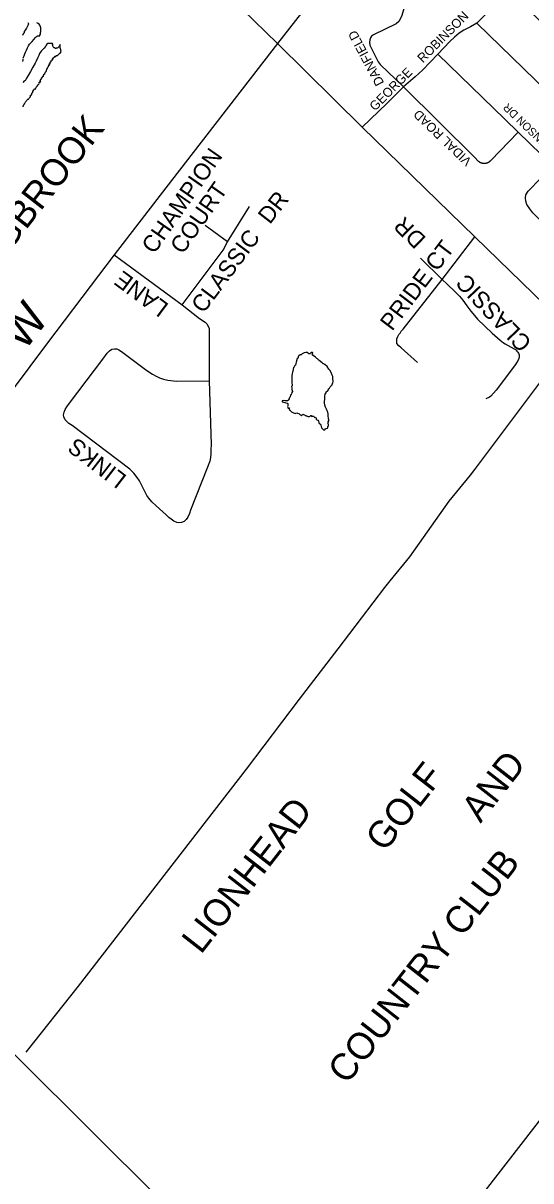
# Model space of a CAD drawing. Extents: x 586326 to 623965, y 4819854 to 4857850.
# Drawn here: x 597005 to 597763, y 4832762 to 4834491 of the extents above; entities that cross this region are included whole.
import ezdxf

# ---------------------------------------------------------------- set-up
doc = ezdxf.new("R2010")
doc.units = 0
for name, color, linetype in [('Lots_Concessions', 7, 'Continuous'), ('Major Rds and Hwys', 7, 'Continuous'), ('Major Rds Lbls', 7, 'Continuous'), ('Minor Rd Lbls', 7, 'Continuous'), ('Minor Rds', 7, 'Continuous'), ('Proposed Secondary Rds', 7, 'Continuous'), ('Pts of Interest', 7, 'Continuous'), ('SWM Ponds', 7, 'Continuous')]:
    doc.layers.add(name, color=color, linetype=linetype)

msp = doc.modelspace()

# ---------------------------------------------------------------- linework, layer by layer
at = {"layer": 'Lots_Concessions'}
for p, q in [((597679.2, 4833824.5), (597830.4, 4834026.5)), ((597673, 4833816.2), (597679.2, 4833824.5)), ((597640.9, 4833777.4), (597673, 4833816.2)), ((597582.2, 4833694.3), (597640.9, 4833777.4)), ((597553.1, 4833658.3), (597582.2, 4833694.3)), ((597475.4, 4833556.9), (597545.2, 4833648.5)), ((597545.2, 4833648.5), (597553.1, 4833658.3)), ((597417.8, 4833481.5), (597475.4, 4833556.9)), ((597338.7, 4833376.9), (597417.8, 4833481.5)), ((597088.1, 4833053.3), (597338.7, 4833376.9)), ((597010.2, 4832954.5), (597088.1, 4833053.3)), ((597478.9, 4832469.2), (597897.6, 4833009.7))]:
    msp.add_line(p, q, dxfattribs=at)
at = {"layer": 'Major Rds and Hwys'}
for points in [[(597524.5, 4834639.5), (597384.7, 4834460.6)], [(597384.7, 4834460.6), (597218.3, 4834245), (597141.1, 4834145)], [(597141.1, 4834145), (597117.7, 4834114), (597041.9, 4834013.5), (596963.5, 4833909.6)], [(597416.6, 4832528.7), (597001.7, 4832942.3), (596973.6, 4832970), (596862.2, 4833079.8)]]:
    msp.add_lwpolyline(points, dxfattribs=at)
at = {"layer": 'Minor Rds'}
for points in [[(597843.1, 4834430.7), (597738.2, 4834531.5), (597733.6, 4834533.8), (597729.6, 4834534), (597725.4, 4834532.4), (597720.6, 4834529.4), (597682.4, 4834490.7)], [(597573.4, 4834512.1), (597570.1, 4834500.9), (597565.8, 4834493.3), (597561.9, 4834489.8), (597528.3, 4834473.5), (597525.2, 4834471.3), (597523.8, 4834468.8), (597522.5, 4834466.2), (597522.1, 4834462.4), (597522.9, 4834458), (597534.9, 4834433.3), (597538.3, 4834428.9), (597572.9, 4834395.6)], [(597682.4, 4834490.7), (597672.6, 4834485.4), (597663.1, 4834480.5), (597656.1, 4834476), (597648.8, 4834470.1), (597641.9, 4834463.6), (597624.3, 4834444.5)], [(597682.4, 4834490.7), (597874.5, 4834303.9)], [(597624.3, 4834444.5), (597601, 4834420.8), (597590.1, 4834410.5), (597572.9, 4834395.6)], [(597624.3, 4834444.5), (597724.3, 4834347.4), (597744.2, 4834328.2)], [(597572.9, 4834395.6), (597548.2, 4834371.1), (597511.2, 4834335.5)], [(597572.9, 4834395.6), (597679.6, 4834289.7), (597683.9, 4834285.5), (597684, 4834285.4), (597684.1, 4834285.4), (597684.2, 4834285.3), (597684.2, 4834285.2), (597684.3, 4834285.1), (597684.4, 4834285.1), (597684.5, 4834285), (597684.5, 4834284.9), (597684.6, 4834284.9), (597684.7, 4834284.8), (597684.8, 4834284.8), (597684.8, 4834284.7), (597684.9, 4834284.6), (597685, 4834284.6), (597685.1, 4834284.5), (597685.2, 4834284.4), (597685.2, 4834284.4), (597685.3, 4834284.3), (597685.4, 4834284.3), (597685.5, 4834284.2), (597685.6, 4834284.1), (597685.7, 4834284.1), (597685.7, 4834284), (597685.8, 4834284), (597685.9, 4834283.9), (597686, 4834283.9), (597686.1, 4834283.8), (597686.2, 4834283.8), (597686.2, 4834283.7), (597686.3, 4834283.6), (597686.4, 4834283.6), (597686.5, 4834283.5), (597686.6, 4834283.5), (597686.7, 4834283.4), (597686.8, 4834283.4), (597686.9, 4834283.3), (597686.9, 4834283.3), (597687, 4834283.2), (597687.1, 4834283.2), (597687.2, 4834283.2), (597687.3, 4834283.1), (597687.4, 4834283.1), (597687.5, 4834283), (597687.6, 4834283), (597687.7, 4834282.9), (597687.8, 4834282.9), (597687.9, 4834282.8), (597687.9, 4834282.8), (597688, 4834282.8), (597688.1, 4834282.7), (597688.2, 4834282.7), (597688.3, 4834282.7), (597688.4, 4834282.6), (597688.5, 4834282.6), (597688.6, 4834282.5), (597688.7, 4834282.5), (597688.8, 4834282.5), (597688.9, 4834282.4), (597689, 4834282.4), (597689.1, 4834282.4), (597689.2, 4834282.3), (597689.3, 4834282.3), (597689.4, 4834282.3), (597689.5, 4834282.3), (597689.6, 4834282.2), (597689.7, 4834282.2), (597689.7, 4834282.2), (597689.8, 4834282.1), (597689.9, 4834282.1), (597690, 4834282.1), (597690.1, 4834282.1), (597690.2, 4834282), (597690.3, 4834282), (597690.4, 4834282), (597690.5, 4834282), (597690.6, 4834282), (597690.7, 4834281.9), (597690.8, 4834281.9), (597690.9, 4834281.9), (597691, 4834281.9), (597691.1, 4834281.9), (597691.2, 4834281.8), (597691.3, 4834281.8), (597691.4, 4834281.8), (597691.5, 4834281.8), (597691.6, 4834281.8), (597691.7, 4834281.8), (597691.8, 4834281.8), (597691.9, 4834281.8), (597692, 4834281.7), (597692.1, 4834281.7), (597692.2, 4834281.7), (597692.3, 4834281.7), (597692.4, 4834281.7), (597692.5, 4834281.7), (597692.6, 4834281.7), (597692.7, 4834281.7), (597692.8, 4834281.7), (597692.9, 4834281.7), (597693, 4834281.7), (597693.1, 4834281.7), (597693.2, 4834281.7), (597693.3, 4834281.7), (597693.4, 4834281.7), (597693.5, 4834281.7), (597693.6, 4834281.7), (597693.7, 4834281.7), (597693.8, 4834281.7), (597693.9, 4834281.7), (597694, 4834281.7), (597694.1, 4834281.7), (597694.2, 4834281.7), (597694.4, 4834281.7), (597694.5, 4834281.7), (597694.6, 4834281.7), (597694.7, 4834281.7), (597694.8, 4834281.8), (597694.9, 4834281.8), (597695, 4834281.8), (597695.1, 4834281.8), (597695.2, 4834281.8), (597695.3, 4834281.8), (597695.4, 4834281.8), (597695.5, 4834281.8), (597695.6, 4834281.9), (597695.7, 4834281.9), (597695.8, 4834281.9), (597695.9, 4834281.9), (597696, 4834281.9), (597696, 4834282), (597696.1, 4834282), (597696.2, 4834282), (597696.3, 4834282), (597696.4, 4834282), (597696.5, 4834282.1), (597696.6, 4834282.1), (597696.7, 4834282.1), (597696.8, 4834282.1), (597696.9, 4834282.2), (597697, 4834282.2), (597697.1, 4834282.2), (597697.2, 4834282.3), (597697.3, 4834282.3), (597697.4, 4834282.3), (597697.5, 4834282.3), (597697.6, 4834282.4), (597697.7, 4834282.4), (597697.8, 4834282.4), (597697.9, 4834282.5), (597698, 4834282.5), (597698.1, 4834282.5), (597698.2, 4834282.6), (597698.3, 4834282.6), (597698.4, 4834282.7), (597698.5, 4834282.7), (597698.6, 4834282.7), (597698.6, 4834282.8), (597698.7, 4834282.8), (597698.8, 4834282.9), (597698.9, 4834282.9), (597699, 4834282.9), (597699.1, 4834283), (597699.2, 4834283), (597699.3, 4834283.1), (597699.4, 4834283.1), (597699.5, 4834283.2), (597699.6, 4834283.2), (597699.6, 4834283.2), (597699.7, 4834283.3), (597699.8, 4834283.3), (597699.9, 4834283.4), (597700, 4834283.4), (597700.1, 4834283.5), (597700.2, 4834283.5), (597700.3, 4834283.6), (597700.4, 4834283.6), (597700.4, 4834283.7), (597700.5, 4834283.8), (597700.6, 4834283.8), (597700.7, 4834283.9), (597700.8, 4834283.9), (597700.9, 4834284), (597700.9, 4834284), (597701, 4834284.1), (597701.1, 4834284.1), (597701.2, 4834284.2), (597701.3, 4834284.3), (597701.4, 4834284.3), (597701.4, 4834284.4), (597701.5, 4834284.4), (597701.6, 4834284.5), (597701.7, 4834284.6), (597701.8, 4834284.6), (597701.8, 4834284.7), (597701.9, 4834284.8), (597702, 4834284.8), (597702.1, 4834284.9), (597702.1, 4834285), (597702.2, 4834285), (597702.3, 4834285.1), (597702.4, 4834285.2), (597702.4, 4834285.2), (597702.5, 4834285.3), (597702.6, 4834285.4), (597702.7, 4834285.4), (597702.7, 4834285.5), (597702.8, 4834285.6), (597702.9, 4834285.6), (597703, 4834285.7), (597703, 4834285.8), (597744.2, 4834328.2)], [(597744.2, 4834328.2), (597795.9, 4834277.7)], [(597797.2, 4834176.7), (597765.8, 4834207.6), (597761.2, 4834213.4), (597757, 4834220.1), (597755.4, 4834225), (597755, 4834229.9), (597755.5, 4834234.6), (597759, 4834239.8), (597795.9, 4834277.7)], [(597310.5, 4834164.4), (597343.1, 4834216.9)], [(597310.5, 4834164.4), (597277, 4834189)], [(597630.8, 4834108.1), (597679.4, 4834172)], [(597242.6, 4834070.2), (597303.9, 4834152.1), (597310.5, 4834164.4)], [(597141.1, 4834145), (597242.6, 4834070.2)], [(597598.3, 4834139.8), (597630.8, 4834108.1)], [(597594, 4833984.2), (597569.2, 4834006.1), (597566, 4834009.1), (597563.1, 4834012.4), (597562.7, 4834015.3), (597563, 4834019.5), (597564.4, 4834022.9), (597566.1, 4834026.2), (597567.7, 4834028.2), (597569.5, 4834030.9), (597572.5, 4834033.8), (597630.8, 4834108.1)], [(597630.8, 4834108.1), (597637.8, 4834101.3), (597650, 4834089.6), (597656.5, 4834083.1), (597661.3, 4834077.3), (597667.6, 4834068.7), (597673.4, 4834061), (597678.7, 4834054.3), (597683.5, 4834048.7), (597705.4, 4834027.8)], [(597242.6, 4834070.2), (597268.7, 4834050.1), (597277, 4834044.3), (597279.6, 4834041.8), (597281.5, 4834038.7), (597282.8, 4834034.9), (597283.1, 4834030.6), (597282.9, 4834021.6), (597282.9, 4833956.6)], [(597705.4, 4834027.8), (597716.9, 4834017.6), (597722.1, 4834013.5), (597724.7, 4834012.1), (597738, 4834004.6), (597739.8, 4834003.5), (597741.1, 4834002.4), (597742.2, 4834001.2), (597743.3, 4833999.7), (597744.4, 4833997.9), (597745.3, 4833995.7), (597745.4, 4833994.3), (597745.4, 4833992.6), (597744.9, 4833990.4), (597744, 4833987.9), (597741.7, 4833983.7), (597739.9, 4833981.3), (597711.2, 4833942.8), (597703.1, 4833933.7), (597701.2, 4833932.4), (597695.9, 4833929.9)], [(597237.9, 4833744.6), (597234.5, 4833745.3), (597230.5, 4833747.3), (597226.2, 4833750.2), (597222.8, 4833752.8), (597218.7, 4833756.6), (597203.9, 4833770.3), (597197.5, 4833776.2), (597193.1, 4833781.5), (597190.1, 4833785.6), (597187.6, 4833790.5), (597183, 4833799.4), (597178.8, 4833807.6), (597175.5, 4833812.5), (597170.5, 4833818.9), (597164.4, 4833824.9), (597078.6, 4833890), (597073.7, 4833893.1), (597070.9, 4833895.5), (597068, 4833898.7), (597066.2, 4833903), (597065.5, 4833906.1), (597066.5, 4833910.1), (597068.1, 4833914.2), (597070.6, 4833918.2), (597074.7, 4833923.6), (597124.2, 4833989.3), (597131, 4833998.1), (597134.1, 4834001.8), (597137.8, 4834004.3), (597141.9, 4834004.8), (597145.3, 4834004.4), (597148.3, 4834003), (597152.3, 4834000.4), (597158.3, 4833996), (597190, 4833972.3), (597198.2, 4833966.8), (597203.7, 4833963.9), (597209, 4833961.5), (597214.7, 4833959.4), (597221.4, 4833957.8), (597234.1, 4833956.5), (597282.9, 4833956.6)], [(597282.9, 4833956.6), (597285.9, 4833861.6), (597285.6, 4833853.6), (597285.3, 4833847.9), (597284.8, 4833842.4), (597283.8, 4833836.8), (597280.7, 4833828), (597255, 4833763.5), (597253.7, 4833758.6), (597251.3, 4833753.1), (597248.9, 4833749.8), (597245.5, 4833747), (597241.8, 4833745.3), (597237.9, 4833744.6)]]:
    msp.add_lwpolyline(points, dxfattribs=at)
at = {"layer": 'Proposed Secondary Rds'}
for points in [[(597384.7, 4834460.6), (597123.6, 4834715)], [(597511.2, 4834335.5), (597384.7, 4834460.6)], [(597679.4, 4834172), (597511.2, 4834335.5)], [(597819.1, 4834036.2), (597679.4, 4834172)]]:
    msp.add_lwpolyline(points, dxfattribs=at)
at = {"layer": 'SWM Ponds'}
for points in [[(597012.3, 4834491.8), (597013.2, 4834489.8), (597013.1, 4834488.5), (597011.9, 4834486.3), (597010.3, 4834483.5), (597008.6, 4834480.6), (597007, 4834478.2), (597007, 4834477.1), (597005.6, 4834474.9), (597004.6, 4834472.6)], [(597005.4, 4834438.8), (597005.8, 4834440.3), (597006.9, 4834442.3), (597007.9, 4834445.1), (597009.1, 4834447.5), (597010.4, 4834450.5), (597011.8, 4834453.9), (597013.5, 4834457), (597015.1, 4834459.7), (597016.7, 4834461.5), (597019, 4834463.5), (597021.4, 4834466.7), (597023.7, 4834469.2), (597025.4, 4834470.9), (597026.7, 4834471.9), (597027.5, 4834472.1), (597028.8, 4834471.7), (597030.2, 4834472), (597030.5, 4834472.8), (597031.1, 4834474.4), (597031.4, 4834475.8), (597031.5, 4834477), (597031.9, 4834478.6), (597031.8, 4834480.4), (597031.8, 4834482), (597031.7, 4834483.8), (597031.4, 4834485.2), (597031, 4834486.8), (597030.2, 4834488.1), (597029.2, 4834489.3), (597028.1, 4834490.3), (597025.9, 4834491.5)], [(597004.7, 4834366.9), (597005.8, 4834366.8), (597006.1, 4834367.4), (597006.2, 4834368), (597006.6, 4834368.7), (597006.9, 4834369.8), (597007.5, 4834369.7), (597007.4, 4834371.1), (597008.5, 4834371.3), (597008.2, 4834371.8), (597008.3, 4834372.4), (597008.9, 4834373.5), (597009.9, 4834374.6), (597010.6, 4834374.8), (597011.1, 4834375.4), (597011.7, 4834376.3), (597012.4, 4834377.3), (597013.4, 4834377.6), (597014, 4834378.3), (597014.8, 4834379.3), (597015.7, 4834380.6), (597016.4, 4834382), (597016.4, 4834383.1), (597017.3, 4834383.4), (597017.8, 4834384), (597018.2, 4834385.1), (597018.5, 4834386.2), (597018.9, 4834387), (597019.7, 4834387.2), (597020.1, 4834387.8), (597020.1, 4834388.9), (597020.7, 4834390.2), (597020.7, 4834391.1), (597021.3, 4834391.1), (597021.9, 4834391.6), (597022, 4834392.2), (597022.6, 4834392.7), (597023.3, 4834392.4), (597023.8, 4834392.7), (597024.2, 4834393.6), (597024.9, 4834394.7), (597025.1, 4834395.4), (597026.6, 4834396.7), (597027.9, 4834398.6), (597028.7, 4834400), (597029.2, 4834401), (597028.9, 4834401.4), (597029.3, 4834402), (597029.4, 4834402.6), (597029.4, 4834403), (597030, 4834402.6), (597030.6, 4834402.4), (597030.7, 4834402.8), (597030.9, 4834403.3), (597030.6, 4834403.8), (597030.7, 4834404.3), (597031.3, 4834404), (597031.6, 4834404.5), (597031.4, 4834404.7), (597030.8, 4834404.8), (597030.6, 4834405.1), (597030.7, 4834405.4), (597031.2, 4834405.4), (597031.2, 4834405.8), (597031.3, 4834406.3), (597031.7, 4834406.6), (597031.8, 4834407.1), (597032.4, 4834407.3), (597032.8, 4834407.6), (597032.7, 4834408), (597033, 4834408.3), (597032.9, 4834408.7), (597033, 4834409.1), (597033.6, 4834409.2), (597033.8, 4834409.6), (597033.8, 4834410.3), (597034.4, 4834410.5), (597034.7, 4834410.7), (597034.7, 4834411.1), (597034.8, 4834411.6), (597035.5, 4834411.4), (597036, 4834411.5), (597035.8, 4834411.9), (597035.9, 4834412.2), (597035.8, 4834412.6), (597035.8, 4834413.1), (597036.3, 4834413.4), (597036.2, 4834413.8), (597036.3, 4834414.3), (597036.4, 4834414.7), (597036.9, 4834414.6), (597037.3, 4834414.8), (597037.6, 4834415.3), (597037.5, 4834415.8), (597037.6, 4834416.1), (597038, 4834416), (597038.3, 4834416.2), (597038.3, 4834416.6), (597038.4, 4834416.9), (597038.5, 4834417.4), (597038.8, 4834417.5), (597038.9, 4834417.8), (597039, 4834418.3), (597039.4, 4834418.3), (597039.6, 4834418.5), (597039.7, 4834418.9), (597039.7, 4834419.4), (597040.2, 4834419.6), (597040.4, 4834420.2), (597040.3, 4834420.7), (597040.1, 4834421.2), (597041, 4834421.4), (597041, 4834421.8), (597040.7, 4834422.6), (597041.1, 4834422.8), (597041.5, 4834423), (597041.4, 4834423.2), (597041.8, 4834423.4), (597041.8, 4834423.8), (597041.8, 4834424.2), (597042.2, 4834424.4), (597042.4, 4834425.3), (597042.8, 4834425.4), (597042.8, 4834425.7), (597043.2, 4834425.9), (597043.2, 4834426.4), (597043.1, 4834426.8), (597043.1, 4834427.2), (597043.7, 4834427.2), (597043.7, 4834428), (597044.2, 4834427.9), (597044.6, 4834428.1), (597044.6, 4834428.6), (597044.4, 4834429.1), (597044.5, 4834430), (597045.6, 4834430), (597045.9, 4834430.4), (597046, 4834431.3), (597046, 4834432.4), (597046.8, 4834433.1), (597046.8, 4834433.7), (597047.2, 4834433.8), (597047.2, 4834434.2), (597047.1, 4834434.4), (597047.1, 4834434.9), (597048.2, 4834434.8), (597048.2, 4834435.3), (597048.9, 4834435.6), (597048.8, 4834435.8), (597048.8, 4834436.1), (597049.3, 4834436.1), (597049.5, 4834436.4), (597049.4, 4834436.7), (597049.4, 4834437.1), (597049.4, 4834437.5), (597049.5, 4834437.7), (597050.1, 4834437.8), (597049.8, 4834438.1), (597049.6, 4834438.4), (597050.2, 4834438.9), (597050.9, 4834438.9), (597051.2, 4834439.2), (597051.3, 4834439.6), (597051.8, 4834439.9), (597052.2, 4834440.6), (597052.5, 4834440.4), (597053.4, 4834440.7), (597053.1, 4834441.1), (597052.5, 4834441.2), (597052.7, 4834441.5), (597053.3, 4834441.5), (597053.9, 4834441.2), (597054.6, 4834441.6), (597054.8, 4834441.9), (597055.1, 4834442.4), (597055.7, 4834442.6), (597056.8, 4834442.6), (597057.4, 4834443), (597057.6, 4834443.5), (597058.1, 4834444.1), (597058.4, 4834444.3), (597059.1, 4834445.2), (597060.1, 4834446.1), (597060.9, 4834446.4), (597061.7, 4834446.6), (597061.7, 4834447.2), (597061.8, 4834447.9), (597061.9, 4834448.6), (597062.3, 4834449.1), (597061.9, 4834449.8), (597061.8, 4834450.4), (597061.9, 4834451.5), (597061.3, 4834452.5), (597060.8, 4834454), (597060.5, 4834455), (597060.5, 4834456), (597060.6, 4834456.8), (597060.8, 4834458.3), (597060.5, 4834459), (597060.2, 4834458.1), (597059.7, 4834456.9), (597059.3, 4834456.4), (597058.5, 4834455.3), (597057.8, 4834454.6), (597057, 4834454), (597056.2, 4834453.7), (597055.4, 4834453.6), (597054.7, 4834453.7), (597054.3, 4834453.1), (597053.8, 4834453.1), (597053.2, 4834453.7), (597052.6, 4834453.9), (597051.9, 4834454.2), (597051.2, 4834454.6), (597050.7, 4834455.1), (597050.1, 4834455.7), (597049.9, 4834456.3), (597049.7, 4834457.3), (597049.6, 4834458.2), (597049.4, 4834459.4), (597049.5, 4834460.2), (597049, 4834460.3), (597047.8, 4834460.5), (597046.1, 4834460.3), (597043.8, 4834460.4), (597042.1, 4834460.4), (597040.7, 4834459.6), (597039.9, 4834458), (597039.1, 4834456.6), (597038.4, 4834455.3), (597036.6, 4834453.5), (597034.8, 4834451.5), (597032.3, 4834448.9), (597030.1, 4834445.7), (597028.8, 4834442.7), (597026.7, 4834438.4), (597024.7, 4834434.3), (597023.4, 4834431.2), (597020, 4834425), (597016.4, 4834418.8), (597013, 4834412.8), (597010.7, 4834408.8), (597009.3, 4834406.3), (597007.9, 4834404.6), (597006.2, 4834403.1), (597005.4, 4834401.9)], [(597004.8, 4834433.8), (597005.7, 4834436.1), (597005.3, 4834437.3)]]:
    msp.add_lwpolyline(points, dxfattribs=at)
msp.add_lwpolyline([(597396, 4833927.1), (597394, 4833927.4), (597392.1, 4833926.9), (597392.1, 4833925.7), (597394.1, 4833925), (597399.2, 4833923.4), (597400, 4833923.3), (597400.2, 4833922.9), (597400.4, 4833922.2), (597400.1, 4833919.5), (597400, 4833918.6), (597400.1, 4833917.5), (597400.2, 4833916.6), (597400.7, 4833915.9), (597401.4, 4833915.8), (597402.1, 4833916.2), (597402.6, 4833916.4), (597402.3, 4833915.5), (597402.1, 4833914.7), (597402.4, 4833914.1), (597403.1, 4833913.6), (597403, 4833913), (597403.9, 4833912.5), (597404.7, 4833911.6), (597405.2, 4833911.4), (597405.9, 4833910.7), (597408.6, 4833909), (597410.2, 4833908.4), (597412.1, 4833908.1), (597412.5, 4833908.8), (597413.8, 4833908.9), (597414.8, 4833908.6), (597416.7, 4833908), (597417.4, 4833907.7), (597417.6, 4833907.1), (597418.2, 4833906.6), (597419.3, 4833906.4), (597419.5, 4833905.6), (597420.6, 4833905.1), (597421.3, 4833905.1), (597421.7, 4833905.8), (597422.1, 4833906.6), (597422.9, 4833906.9), (597423.9, 4833906.6), (597425.1, 4833906.1), (597426, 4833905), (597427.1, 4833905.1), (597427.9, 4833904.4), (597428.8, 4833904.5), (597429.3, 4833904.3), (597430.5, 4833903.8), (597431.6, 4833903.6), (597432.5, 4833903.8), (597433.5, 4833904.2), (597434.5, 4833904.9), (597435.2, 4833904.9), (597436.3, 4833903.8), (597437.2, 4833904.3), (597438.4, 4833904.2), (597439.6, 4833903.3), (597439.9, 4833902), (597441, 4833902.4), (597442.1, 4833901.9), (597442.5, 4833900.7), (597442.8, 4833899), (597444.9, 4833898.1), (597446, 4833896.4), (597446.5, 4833894.6), (597447.2, 4833893.3), (597449.2, 4833892.3), (597449.6, 4833890.7), (597450.8, 4833886.5), (597452.7, 4833884.6), (597453.7, 4833883.6), (597455.5, 4833883.8), (597456.3, 4833885.4), (597457.6, 4833885.9), (597459.5, 4833886.3), (597460, 4833887.1), (597460.2, 4833888.6), (597461, 4833889.7), (597461.2, 4833891.8), (597460.2, 4833893.4), (597460.9, 4833893.9), (597460.7, 4833895.6), (597461.4, 4833897), (597461.5, 4833898.6), (597460.9, 4833900.1), (597460.3, 4833905.1), (597460.3, 4833907.4), (597459.9, 4833909.9), (597458.9, 4833912.2), (597457.8, 4833914.6), (597456.6, 4833917.4), (597455.6, 4833920.4), (597455.1, 4833923.9), (597454.9, 4833925.2), (597455.1, 4833926.6), (597455.4, 4833929.2), (597455.5, 4833931.4), (597455.6, 4833933.7), (597456, 4833937), (597456.8, 4833938.6), (597457.5, 4833939), (597457.4, 4833940.6), (597459.3, 4833941.5), (597461, 4833943.5), (597461.2, 4833944.9), (597462.1, 4833945.2), (597462.3, 4833946.1), (597463.1, 4833946.8), (597463.7, 4833948.1), (597464.6, 4833949), (597465.6, 4833949.7), (597466.6, 4833951.1), (597466.6, 4833952.4), (597467.3, 4833953), (597467.7, 4833953.8), (597468.1, 4833955.9), (597467.4, 4833960.3), (597467.7, 4833961.2), (597467.3, 4833963.1), (597466.6, 4833965.2), (597465, 4833969.3), (597462.9, 4833973), (597461.7, 4833974.5), (597458.8, 4833978.2), (597455.6, 4833981.2), (597454.9, 4833981.3), (597454, 4833982.3), (597452.5, 4833982.8), (597451.4, 4833983.8), (597447.2, 4833987.4), (597444.5, 4833989.9), (597443.4, 4833990.3), (597441.6, 4833992.4), (597437.9, 4833994.5), (597438, 4833995.1), (597437.2, 4833995.2), (597436.6, 4833995.8), (597437, 4833996.7), (597437.8, 4833998.8), (597436.4, 4833999.8), (597434.7, 4833998.1), (597433.2, 4833997), (597431.9, 4833997.2), (597429.2, 4833999), (597427.1, 4833999.1), (597424.6, 4833998.8), (597423.8, 4833998.3), (597421.7, 4833997.1), (597420.2, 4833995.8), (597418.6, 4833995.9), (597416.5, 4833994.1), (597415.9, 4833993), (597415.7, 4833992.1), (597415.6, 4833991.1), (597414.7, 4833990.2), (597414.2, 4833990.1), (597413.8, 4833989.3), (597413.9, 4833988.3), (597412.8, 4833984.7), (597412.5, 4833982.5), (597411.7, 4833980), (597410.9, 4833979.6), (597409.5, 4833976.8), (597409, 4833977), (597408.2, 4833973.9), (597407.8, 4833971.2), (597407.3, 4833970), (597406.6, 4833967.7), (597406.1, 4833964.1), (597406.3, 4833959.4), (597406.2, 4833955.3), (597406.6, 4833949.5), (597405.9, 4833948.6), (597406.5, 4833946.4), (597406.3, 4833943.9), (597407.2, 4833941.1), (597406.5, 4833939.3), (597405.8, 4833937.6), (597405.3, 4833936.2), (597404.4, 4833935.9), (597404.2, 4833934.5), (597403.7, 4833933.4), (597403.4, 4833932), (597402.6, 4833931.7), (597402.3, 4833930.9), (597402.1, 4833929.9), (597401.5, 4833928.5), (597401.4, 4833927.9), (597399.9, 4833926.8), (597397.9, 4833926.8)], close=True, dxfattribs=at)

# ---------------------------------------------------------------- texts
at = {"layer": 'Major Rds Lbls'}
msp.add_text('QUEEN ST W', height=50, rotation=52.5926, dxfattribs=at).set_placement((596788, 4833713))
at = {"layer": 'Minor Rd Lbls'}
for s, height, rotation, p in [('GEORGE    ROBINSON', 13.767, 45.1302, (597530.4, 4834358.9)), ('DANFIELD', 13.69, 118.1303, (597544.3, 4834401.7)), ('VIDAL ROAD', 13.69, 136.0741, (597675.7, 4834286)), ('GEORGE ROBINSON DR ', 11.922, 136.0741, (597863.1, 4834242.5)), ('CHAMPION', 25, 55.0707, (597200.9, 4834144.9)), ('COURT', 25, 55.0707, (597243.5, 4834144.5)), ('DR', 25, 52.1659, (597373.5, 4834189.4)), ('DR', 25, 135.8216, (597608.1, 4834170)), ('CLASSIC', 25, 53.1302, (597274.4, 4834056.3)), ('PRIDE CT', 25, 52.8175, (597555.9, 4834030)), ('LANE', 25, 143.4054, (597224.2, 4834070.4)), ('CLASSIC', 25, 133.4816, (597765.7, 4834014.7)), ('LINKS', 25, 142.317, (597161.5, 4833814.2))]:
    msp.add_text(s, height=height, rotation=rotation, dxfattribs=at).set_placement(p)
at = {"layer": 'Pts of Interest'}
for s, height, p in [('SPRINGBROOK', 39.984, (596883.2, 4834019.6)), ('GOLF', 39.98, (597544.7, 4833251.9)), ('AND', 39.98, (597687.8, 4833295.4)), ('LIONHEAD', 39.98, (597270.7, 4833099.4)), ('COUNTRY CLUB', 39.984, (597488.4, 4832904.9))]:
    msp.add_text(s, height=height, rotation=52, dxfattribs=at).set_placement(p)

doc.saveas('drawing.dxf')
